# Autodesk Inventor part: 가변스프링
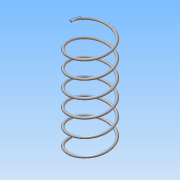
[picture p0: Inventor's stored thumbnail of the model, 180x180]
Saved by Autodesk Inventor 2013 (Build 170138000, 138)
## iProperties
Created: 2016-11
Part Number: 가변스프링
Material: 알루미늄 6061
Document SubType Name: Modeling
Designer: Administrator
Density: 2.71 g/cm^3
Mass: 5.10947 g
Surface Area: 38.028 cm^2
Volume: 1.88541 cm^3
Author: Administrator
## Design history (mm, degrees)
sketch "스케치1"
  geometry: L1 (0, 0)-(16, 0); L2 (16, 0)-(16, 84.368); L3 (16, 84.368)-(0, 84.368); L4 (0, 84.368)-(0, 0); C1 r 1 at (16, 0)
  constraints: 8 end point, 2 parallel, 1 centre point, 1 coincident, 1 horizontal, 1 perpendicular
  dimensions: "d0" = 84.36759 distance of L1.end L2.end (derived); "d2" = 16 distance of L2.end L3.end; "d3" = 2 diameter of C1
feature "코일1" sketch "스케치1" pitch "d4" = 10; turns "d6" = 6; dims "d5" = 84.36759 (= d0), "d7" = 0, angle "d8" = 90 deg, angle "d9" = 90 deg, "d10" = 0, "d11" = 0
sketch "스케치2"
  geometry: L1 (-15.54, 0)-(52.453, 0); L2 (52.453, 0)-(52.453, -84.368); L3 (52.453, -84.368)-(-15.54, -84.368); L4 (-15.54, -84.368)-(-15.54, 0); 5 further points
  constraints: 8 end point, 2 horizontal alignment, 2 parallel, 2 point on line, 1 horizontal, 1 perpendicular
extrude "돌출1" sketch "스케치2" stored distance "d12" = 0; taper "d13" = 0 deg
node "솔리드1"
